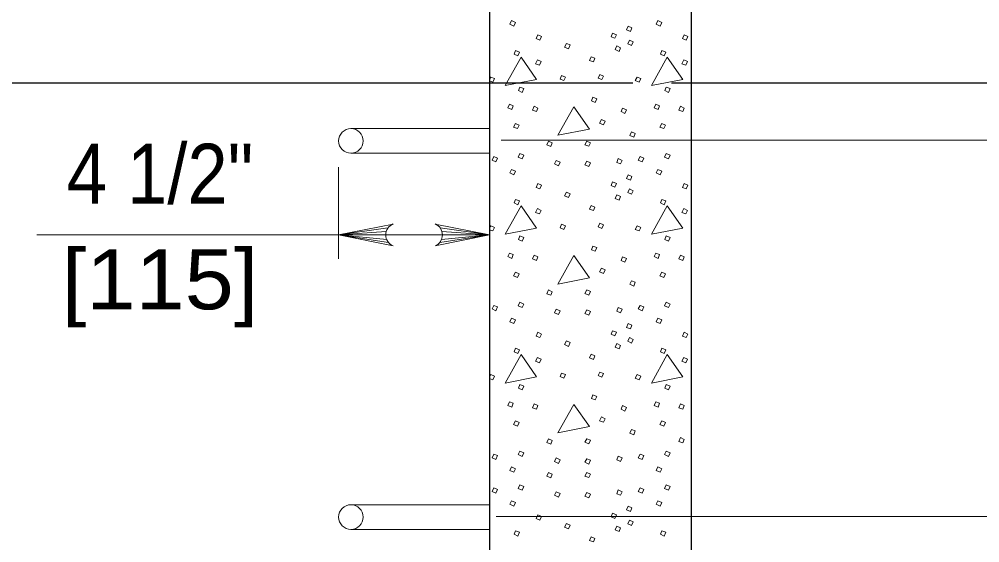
# Model space of a CAD drawing. Extents: x 1083.1 to 1123, y 697.4 to 741.4.
# Drawn here: x 1094.221 to 1096.714, y 723.357 to 724.717 of the extents above; entities that cross this region are included whole.
import ezdxf
from ezdxf.enums import TextEntityAlignment as Align

# ---------------------------------------------------------------- set-up
doc = ezdxf.new("R2010")
doc.units = 0
doc.header["$LTSCALE"] = 0.062
doc.linetypes.add('LONG_DASHED', pattern=[7.5, 6, -1.5])
doc.layers.add('1', color=7, linetype='Continuous', lineweight=13)

msp = doc.modelspace()

# ---------------------------------------------------------------- linework, layer by layer
at = {"layer": '1'}
for p, q in [((1095.442, 724.56117), (1095.44483, 724.56675)), ((1095.08192, 724.43275), (1095.442, 724.43275)), ((1095.47167, 724.4025), (1097.24158, 724.4025)), ((1095.08192, 724.36883), (1095.442, 724.36883)), ((1095.04992, 724.33283), (1095.04992, 724.09417)), ((1095.17817, 724.17467), (1095.04992, 724.15667)), ((1095.17383, 724.16575), (1095.04992, 724.15667)), ((1095.31383, 724.17467), (1095.442, 724.15667)), ((1095.31817, 724.16575), (1095.442, 724.15667)), ((1095.442, 724.17475), (1095.44483, 724.18033)), ((1094.26675, 724.15667), (1095.442, 724.15667)), ((1095.1725, 724.15667), (1095.04992, 724.15667)), ((1095.17475, 724.14517), (1095.04992, 724.15667)), ((1095.17967, 724.13683), (1095.04992, 724.15667)), ((1095.31233, 724.13683), (1095.442, 724.15667)), ((1095.31725, 724.14517), (1095.442, 724.15667)), ((1095.3195, 724.15667), (1095.442, 724.15667)), ((1095.442, 723.78833), (1095.44483, 723.79392)), ((1095.08192, 723.45583), (1095.442, 723.45583)), ((1095.459, 723.42492), (1097.24158, 723.42492)), ((1095.08192, 723.39183), (1095.442, 723.39183))]:
    msp.add_line(p, q, dxfattribs=at)
at = {"layer": '1', "lineweight": 25}
for p, q in [((1093.0675, 724.55142), (1095.442, 724.55142)), ((1095.96625, 724.55142), (1098.73933, 724.55142))]:
    msp.add_line(p, q, dxfattribs=at)
at = {"layer": '1', "linetype": 'LONG_DASHED', "lineweight": 25}
msp.add_line((1095.442, 724.55142), (1095.96625, 724.55142), dxfattribs=at)
at = {"layer": '1', "lineweight": 25}
for points in [[(1093.0675, 725.37967), (1092.53542, 725.37967), (1092.53542, 721.67958), (1095.96625, 721.67958), (1095.96625, 725.37967)], [(1095.96625, 725.37967), (1095.442, 725.37967), (1095.442, 722.82933)]]:
    msp.add_lwpolyline(points, dxfattribs=at)
at = {"layer": '1'}
for points in [[(1095.49883, 724.71333), (1095.50883, 724.70867), (1095.50483, 724.69933), (1095.49483, 724.704)], [(1095.87867, 724.71333), (1095.88867, 724.70867), (1095.88467, 724.69933), (1095.87467, 724.704)], [(1095.80133, 724.69933), (1095.81133, 724.69467), (1095.80733, 724.68542), (1095.79733, 724.68933)], [(1095.56675, 724.67675), (1095.57675, 724.67208), (1095.57275, 724.66275), (1095.56275, 724.66675)], [(1095.76133, 724.68075), (1095.77133, 724.67675), (1095.76733, 724.66742), (1095.75733, 724.67142)], [(1095.80467, 724.66275), (1095.81467, 724.65808), (1095.81067, 724.64875), (1095.80067, 724.65342)], [(1095.94658, 724.67675), (1095.95658, 724.67208), (1095.95258, 724.66275), (1095.94258, 724.66675)], [(1095.64142, 724.65408), (1095.65142, 724.65008), (1095.64675, 724.64008), (1095.63675, 724.64475)], [(1095.772, 724.64742), (1095.782, 724.64275), (1095.778, 724.63342), (1095.768, 724.63808)], [(1095.5235, 724.61875), (1095.48217, 724.54483), (1095.56408, 724.56075)], [(1095.5095, 724.63542), (1095.5195, 724.63142), (1095.5155, 724.62142), (1095.5055, 724.62608)], [(1095.70542, 724.61942), (1095.71542, 724.61542), (1095.71142, 724.60608), (1095.70142, 724.61008)], [(1095.90325, 724.61875), (1095.862, 724.54483), (1095.94392, 724.56075)], [(1095.88933, 724.63542), (1095.89925, 724.63142), (1095.89533, 724.62142), (1095.88533, 724.62608)], [(1095.56608, 724.61142), (1095.57608, 724.60675), (1095.57142, 724.59742), (1095.56142, 724.60142)], [(1095.94592, 724.61142), (1095.95592, 724.60675), (1095.95125, 724.59742), (1095.94125, 724.60142)], [(1095.62875, 724.57075), (1095.63875, 724.56675), (1095.63475, 724.55742), (1095.62475, 724.56142)], [(1095.728, 724.57342), (1095.738, 724.56942), (1095.73333, 724.56008), (1095.72342, 724.56408)], [(1095.82467, 724.56675), (1095.83467, 724.56275), (1095.83, 724.55342), (1095.82, 724.55742)], [(1095.52083, 724.54075), (1095.53083, 724.53683), (1095.52683, 724.52683), (1095.51683, 724.5315)], [(1095.90058, 724.54075), (1095.91058, 724.53683), (1095.90658, 724.52683), (1095.89658, 724.5315)], [(1095.71008, 724.51417), (1095.72008, 724.51017), (1095.71608, 724.50083), (1095.70608, 724.50483)], [(1095.4935, 724.49617), (1095.5035, 724.49217), (1095.4995, 724.48217), (1095.4895, 724.48683)], [(1095.55742, 724.49083), (1095.56742, 724.48617), (1095.56342, 724.47683), (1095.55342, 724.48083)], [(1095.66075, 724.4895), (1095.61942, 724.4155), (1095.70142, 724.4315)], [(1095.87333, 724.49617), (1095.88333, 724.49217), (1095.87933, 724.48217), (1095.86933, 724.48683)], [(1095.93725, 724.49083), (1095.94725, 724.48617), (1095.94325, 724.47683), (1095.93325, 724.48083)], [(1095.78733, 724.48617), (1095.79733, 724.4815), (1095.79333, 724.47217), (1095.78333, 724.47683)], [(1095.50883, 724.44617), (1095.51883, 724.44217), (1095.51417, 724.43283), (1095.50417, 724.43683)], [(1095.732, 724.45683), (1095.742, 724.45217), (1095.73733, 724.44283), (1095.72733, 724.44683)], [(1095.88867, 724.44617), (1095.89867, 724.44217), (1095.894, 724.43283), (1095.884, 724.43683)], [(1095.81, 724.42417), (1095.82, 724.42017), (1095.816, 724.41017), (1095.806, 724.41483)], [(1095.59475, 724.40017), (1095.60475, 724.39558), (1095.60075, 724.38625), (1095.59075, 724.39025)], [(1095.69408, 724.40017), (1095.70408, 724.39617), (1095.69942, 724.38692), (1095.68942, 724.39083)], [(1095.52083, 724.36825), (1095.53083, 724.36358), (1095.52617, 724.35425), (1095.51617, 724.35892)], [(1095.90058, 724.36825), (1095.91058, 724.36358), (1095.90592, 724.35425), (1095.896, 724.35892)], [(1095.45283, 724.36025), (1095.46283, 724.35625), (1095.45817, 724.34625), (1095.44817, 724.35092)], [(1095.61475, 724.35025), (1095.62475, 724.34558), (1095.62075, 724.33625), (1095.61075, 724.34092)], [(1095.69408, 724.34825), (1095.70408, 724.34425), (1095.69942, 724.33425), (1095.68942, 724.33892)], [(1095.776, 724.35492), (1095.786, 724.35025), (1095.782, 724.34092), (1095.772, 724.34492)], [(1095.83267, 724.36025), (1095.84267, 724.35625), (1095.838, 724.34625), (1095.828, 724.35092)], [(1095.49883, 724.32692), (1095.50883, 724.32225), (1095.50483, 724.31292), (1095.49483, 724.31758)], [(1095.87867, 724.32692), (1095.88867, 724.32225), (1095.88467, 724.31292), (1095.87467, 724.31758)], [(1095.56675, 724.29025), (1095.57675, 724.28558), (1095.57275, 724.27625), (1095.56275, 724.28025)], [(1095.76133, 724.29425), (1095.77133, 724.29025), (1095.76733, 724.28092), (1095.75733, 724.28492)], [(1095.80133, 724.31292), (1095.81133, 724.30825), (1095.80733, 724.29892), (1095.79733, 724.30292)], [(1095.94658, 724.29025), (1095.95658, 724.28558), (1095.95258, 724.27625), (1095.94258, 724.28025)], [(1095.64142, 724.26758), (1095.65142, 724.26358), (1095.64675, 724.25358), (1095.63675, 724.25825)], [(1095.80467, 724.27625), (1095.81467, 724.27158), (1095.81067, 724.26225), (1095.80067, 724.26692)], [(1095.5095, 724.249), (1095.5195, 724.245), (1095.5155, 724.235), (1095.5055, 724.23967)], [(1095.772, 724.26092), (1095.782, 724.25625), (1095.778, 724.247), (1095.768, 724.25167)], [(1095.88933, 724.249), (1095.89925, 724.245), (1095.89533, 724.235), (1095.88533, 724.23967)], [(1095.5235, 724.23233), (1095.48217, 724.15833), (1095.56408, 724.17433)], [(1095.56608, 724.225), (1095.57608, 724.22033), (1095.57142, 724.211), (1095.56142, 724.215)], [(1095.70542, 724.233), (1095.71542, 724.229), (1095.71142, 724.21967), (1095.70142, 724.22367)], [(1095.90325, 724.23233), (1095.862, 724.15833), (1095.94392, 724.17433)], [(1095.94592, 724.225), (1095.95592, 724.22033), (1095.95125, 724.211), (1095.94125, 724.215)], [(1095.62875, 724.18433), (1095.63875, 724.18033), (1095.63475, 724.171), (1095.62475, 724.175)], [(1095.728, 724.187), (1095.738, 724.183), (1095.73333, 724.17367), (1095.72342, 724.17767)], [(1095.82467, 724.18033), (1095.83467, 724.17633), (1095.83, 724.167), (1095.82, 724.171)], [(1095.52083, 724.15433), (1095.53083, 724.15033), (1095.52683, 724.14033), (1095.51683, 724.145)], [(1095.90058, 724.15433), (1095.91058, 724.15033), (1095.90658, 724.14033), (1095.89658, 724.145)], [(1095.71008, 724.12767), (1095.72008, 724.12367), (1095.71608, 724.11433), (1095.70608, 724.11833)], [(1095.4935, 724.10967), (1095.5035, 724.10567), (1095.4995, 724.09575), (1095.4895, 724.10042)], [(1095.55742, 724.10442), (1095.56742, 724.09975), (1095.56342, 724.09042), (1095.55342, 724.09442)], [(1095.66075, 724.10308), (1095.61942, 724.02908), (1095.70142, 724.04508)], [(1095.78733, 724.09975), (1095.79733, 724.09508), (1095.79333, 724.08575), (1095.78333, 724.09042)], [(1095.87333, 724.10967), (1095.88333, 724.10567), (1095.87933, 724.09575), (1095.86933, 724.10042)], [(1095.93725, 724.10442), (1095.94725, 724.09975), (1095.94325, 724.09042), (1095.93325, 724.09442)], [(1095.732, 724.07042), (1095.742, 724.06575), (1095.73733, 724.05642), (1095.72733, 724.06042)], [(1095.50883, 724.05975), (1095.51883, 724.05575), (1095.51417, 724.04642), (1095.50417, 724.05042)], [(1095.88867, 724.05975), (1095.89867, 724.05575), (1095.894, 724.04642), (1095.884, 724.05042)], [(1095.81, 724.03775), (1095.82, 724.03375), (1095.816, 724.02375), (1095.806, 724.02842)], [(1095.59475, 724.01375), (1095.60475, 724.00908), (1095.60075, 723.99975), (1095.59075, 724.00375)], [(1095.69408, 724.01375), (1095.70408, 724.00975), (1095.69942, 724.00042), (1095.68942, 724.00442)], [(1095.45283, 723.97375), (1095.46283, 723.96975), (1095.45817, 723.95983), (1095.44817, 723.96442)], [(1095.52083, 723.98175), (1095.53083, 723.97708), (1095.52617, 723.96775), (1095.51617, 723.97242)], [(1095.776, 723.96842), (1095.786, 723.96383), (1095.782, 723.9545), (1095.772, 723.9585)], [(1095.83267, 723.97375), (1095.84267, 723.96975), (1095.838, 723.95983), (1095.828, 723.96442)], [(1095.90058, 723.98175), (1095.91058, 723.97708), (1095.90592, 723.96775), (1095.896, 723.97242)], [(1095.49883, 723.9405), (1095.50883, 723.93583), (1095.50483, 723.9265), (1095.49483, 723.93117)], [(1095.61475, 723.96383), (1095.62475, 723.95917), (1095.62075, 723.94983), (1095.61075, 723.9545)], [(1095.69408, 723.96183), (1095.70408, 723.95783), (1095.69942, 723.94783), (1095.68942, 723.9525)], [(1095.87867, 723.9405), (1095.88867, 723.93583), (1095.88467, 723.9265), (1095.87467, 723.93117)], [(1095.80133, 723.9265), (1095.81133, 723.92183), (1095.80733, 723.9125), (1095.79733, 723.9165)], [(1095.56675, 723.90383), (1095.57675, 723.89917), (1095.57275, 723.88983), (1095.56275, 723.89383)], [(1095.76133, 723.90783), (1095.77133, 723.90383), (1095.76733, 723.8945), (1095.75733, 723.8985)], [(1095.80467, 723.88983), (1095.81467, 723.88517), (1095.81067, 723.87583), (1095.80067, 723.8805)], [(1095.94658, 723.90383), (1095.95658, 723.89917), (1095.95258, 723.88983), (1095.94258, 723.89383)], [(1095.64142, 723.88117), (1095.65142, 723.87717), (1095.64675, 723.86717), (1095.63675, 723.87183)], [(1095.772, 723.8745), (1095.782, 723.86983), (1095.778, 723.8605), (1095.768, 723.86517)], [(1095.5235, 723.84583), (1095.48217, 723.77192), (1095.56408, 723.78792)], [(1095.5095, 723.8625), (1095.5195, 723.8585), (1095.5155, 723.8485), (1095.5055, 723.85317)], [(1095.70542, 723.8465), (1095.71542, 723.8425), (1095.71142, 723.83317), (1095.70142, 723.83717)], [(1095.90325, 723.84583), (1095.862, 723.77192), (1095.94392, 723.78792)], [(1095.88933, 723.8625), (1095.89925, 723.8585), (1095.89533, 723.8485), (1095.88533, 723.85317)], [(1095.56608, 723.8385), (1095.57608, 723.83383), (1095.57142, 723.8245), (1095.56142, 723.8285)], [(1095.94592, 723.8385), (1095.95592, 723.83383), (1095.95125, 723.8245), (1095.94125, 723.8285)], [(1095.62875, 723.79792), (1095.63875, 723.79392), (1095.63475, 723.78458), (1095.62475, 723.78858)], [(1095.728, 723.80058), (1095.738, 723.79658), (1095.73333, 723.78725), (1095.72342, 723.79125)], [(1095.82467, 723.79392), (1095.83467, 723.78992), (1095.83, 723.78058), (1095.82, 723.78458)], [(1095.52083, 723.76792), (1095.53083, 723.76392), (1095.52683, 723.75392), (1095.51683, 723.75858)], [(1095.90058, 723.76792), (1095.91058, 723.76392), (1095.90658, 723.75392), (1095.89658, 723.75858)], [(1095.71008, 723.74125), (1095.72008, 723.73725), (1095.71608, 723.72792), (1095.70608, 723.73192)], [(1095.4935, 723.72325), (1095.5035, 723.71925), (1095.4995, 723.70925), (1095.4895, 723.71392)], [(1095.55742, 723.71792), (1095.56742, 723.71325), (1095.56342, 723.70392), (1095.55342, 723.70792)], [(1095.66075, 723.71658), (1095.61942, 723.64267), (1095.70142, 723.65867)], [(1095.87333, 723.72325), (1095.88333, 723.71925), (1095.87933, 723.70925), (1095.86933, 723.71392)], [(1095.93725, 723.71792), (1095.94725, 723.71325), (1095.94325, 723.70392), (1095.93325, 723.70792)], [(1095.78733, 723.71325), (1095.79733, 723.70858), (1095.79333, 723.69925), (1095.78333, 723.70392)], [(1095.50883, 723.67333), (1095.51883, 723.66933), (1095.51417, 723.66), (1095.50417, 723.664)], [(1095.732, 723.68392), (1095.742, 723.67925), (1095.73733, 723.66992), (1095.72733, 723.674)], [(1095.88867, 723.67333), (1095.89867, 723.66933), (1095.894, 723.66), (1095.884, 723.664)], [(1095.81, 723.65133), (1095.82, 723.64733), (1095.816, 723.63733), (1095.806, 723.642)], [(1095.59475, 723.62733), (1095.60475, 723.62267), (1095.60075, 723.61333), (1095.59075, 723.61733)], [(1095.69408, 723.62733), (1095.70408, 723.62333), (1095.69942, 723.614), (1095.68942, 723.618)], [(1095.93725, 723.63017), (1095.94725, 723.6255), (1095.94325, 723.61625), (1095.93325, 723.62025)], [(1095.52083, 723.59533), (1095.53083, 723.59067), (1095.52617, 723.58133), (1095.51617, 723.586)], [(1095.90058, 723.59533), (1095.91058, 723.59067), (1095.90592, 723.58133), (1095.896, 723.586)], [(1095.45283, 723.58733), (1095.46283, 723.58333), (1095.45817, 723.57333), (1095.44817, 723.578)], [(1095.61475, 723.57733), (1095.62475, 723.57267), (1095.62075, 723.56333), (1095.61075, 723.568)], [(1095.69408, 723.57533), (1095.70408, 723.57133), (1095.69942, 723.56133), (1095.68942, 723.566)], [(1095.776, 723.582), (1095.786, 723.57733), (1095.782, 723.568), (1095.772, 723.572)], [(1095.83267, 723.58733), (1095.84267, 723.58333), (1095.838, 723.57333), (1095.828, 723.578)], [(1095.49883, 723.554), (1095.50883, 723.54933), (1095.50483, 723.54), (1095.49483, 723.54467)], [(1095.87867, 723.554), (1095.88867, 723.54933), (1095.88467, 723.54), (1095.87467, 723.54467)], [(1095.59475, 723.53958), (1095.60475, 723.53492), (1095.60075, 723.52558), (1095.59075, 723.52958)], [(1095.69408, 723.53958), (1095.70408, 723.53558), (1095.69942, 723.52625), (1095.68942, 723.53025)], [(1095.45283, 723.49958), (1095.46283, 723.49558), (1095.45817, 723.48558), (1095.44817, 723.49025)], [(1095.52083, 723.50758), (1095.53083, 723.50292), (1095.52617, 723.49358), (1095.51617, 723.49825)], [(1095.776, 723.49425), (1095.786, 723.48958), (1095.782, 723.48025), (1095.772, 723.48433)], [(1095.83267, 723.49958), (1095.84267, 723.49558), (1095.838, 723.48558), (1095.828, 723.49025)], [(1095.90058, 723.50758), (1095.91058, 723.50292), (1095.90592, 723.49358), (1095.896, 723.49825)], [(1095.49883, 723.46633), (1095.50883, 723.46167), (1095.50483, 723.45233), (1095.49483, 723.457)], [(1095.61475, 723.48958), (1095.62475, 723.48492), (1095.62075, 723.47567), (1095.61075, 723.48025)], [(1095.69408, 723.48758), (1095.70408, 723.48367), (1095.69942, 723.47367), (1095.68942, 723.47833)], [(1095.87867, 723.46633), (1095.88867, 723.46167), (1095.88467, 723.45233), (1095.87467, 723.457)], [(1095.80133, 723.45233), (1095.81133, 723.44767), (1095.80733, 723.43833), (1095.79733, 723.44233)], [(1095.56675, 723.42967), (1095.57675, 723.425), (1095.57275, 723.41567), (1095.56275, 723.41967)], [(1095.76133, 723.43367), (1095.77133, 723.42967), (1095.76733, 723.42033), (1095.75733, 723.42433)], [(1095.64142, 723.407), (1095.65142, 723.403), (1095.64675, 723.393), (1095.63675, 723.39767)], [(1095.772, 723.40033), (1095.782, 723.39567), (1095.778, 723.38633), (1095.768, 723.391)], [(1095.80467, 723.41567), (1095.81467, 723.411), (1095.81067, 723.40167), (1095.80067, 723.40633)], [(1095.5095, 723.38833), (1095.5195, 723.38433), (1095.5155, 723.37433), (1095.5055, 723.379)], [(1095.70542, 723.37233), (1095.71542, 723.36833), (1095.71142, 723.359), (1095.70142, 723.363)], [(1095.88933, 723.38833), (1095.89925, 723.38433), (1095.89533, 723.37433), (1095.88533, 723.379)]]:
    msp.add_lwpolyline(points, close=True, dxfattribs=at)
for points in [[(1095.44483, 724.56675), (1095.45483, 724.56275), (1095.45017, 724.55342), (1095.442, 724.55675)], [(1095.19158, 724.12842), (1095.04992, 724.15667), (1095.19158, 724.185)], [(1095.30042, 724.12842), (1095.442, 724.15667), (1095.30042, 724.185)], [(1095.44483, 724.18033), (1095.45483, 724.17633), (1095.45017, 724.167), (1095.442, 724.17025)], [(1095.44483, 723.79392), (1095.45483, 723.78992), (1095.45017, 723.78058), (1095.442, 723.78383)]]:
    msp.add_lwpolyline(points, dxfattribs=at)
for centre, start, end in [((1095.20299, 724.15673), 112.08782, 247.91395), ((1095.289, 724.15673), 292.08605, 67.91218)]:
    msp.add_arc(centre, 0.03056, start, end, dxfattribs=at)
for centre in [(1095.08194, 724.40081), (1095.08194, 723.42383)]:
    msp.add_ellipse(centre, major_axis=(0.03198, 0), ratio=0.999895, dxfattribs=at)

# ---------------------------------------------------------------- texts
for s, width, p in [('4 1/2"', 0.9, (1094.58654, 724.23742)), ('[115]', 1.1, (1094.58654, 723.96342))]:
    msp.add_text(s, height=0.156, dxfattribs=dict(at, width=width)).set_placement(p, align=Align.CENTER)

doc.saveas('drawing.dxf')
